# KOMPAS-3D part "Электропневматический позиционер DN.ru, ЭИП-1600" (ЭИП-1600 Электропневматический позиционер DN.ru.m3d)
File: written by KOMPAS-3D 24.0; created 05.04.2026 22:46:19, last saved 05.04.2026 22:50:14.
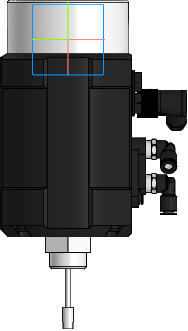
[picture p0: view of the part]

Document properties: Автор: R2D2; Полное имя файла: ЭИП-1600 Электропневматический позиционер DN.ru.cdw

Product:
- Body: Тело 2  | qty 1
    Масса: 9.466594
- Part/product: Электропневматический позиционер DN.ru  | designation ЭИП-1600
    Масса: 0.14
    Раздел спецификации: Прочие изделия
    Форматы листов документа: A3
    Примечание: D900-02742

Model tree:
1. Операция без истории:1

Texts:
  ЭИП-1600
